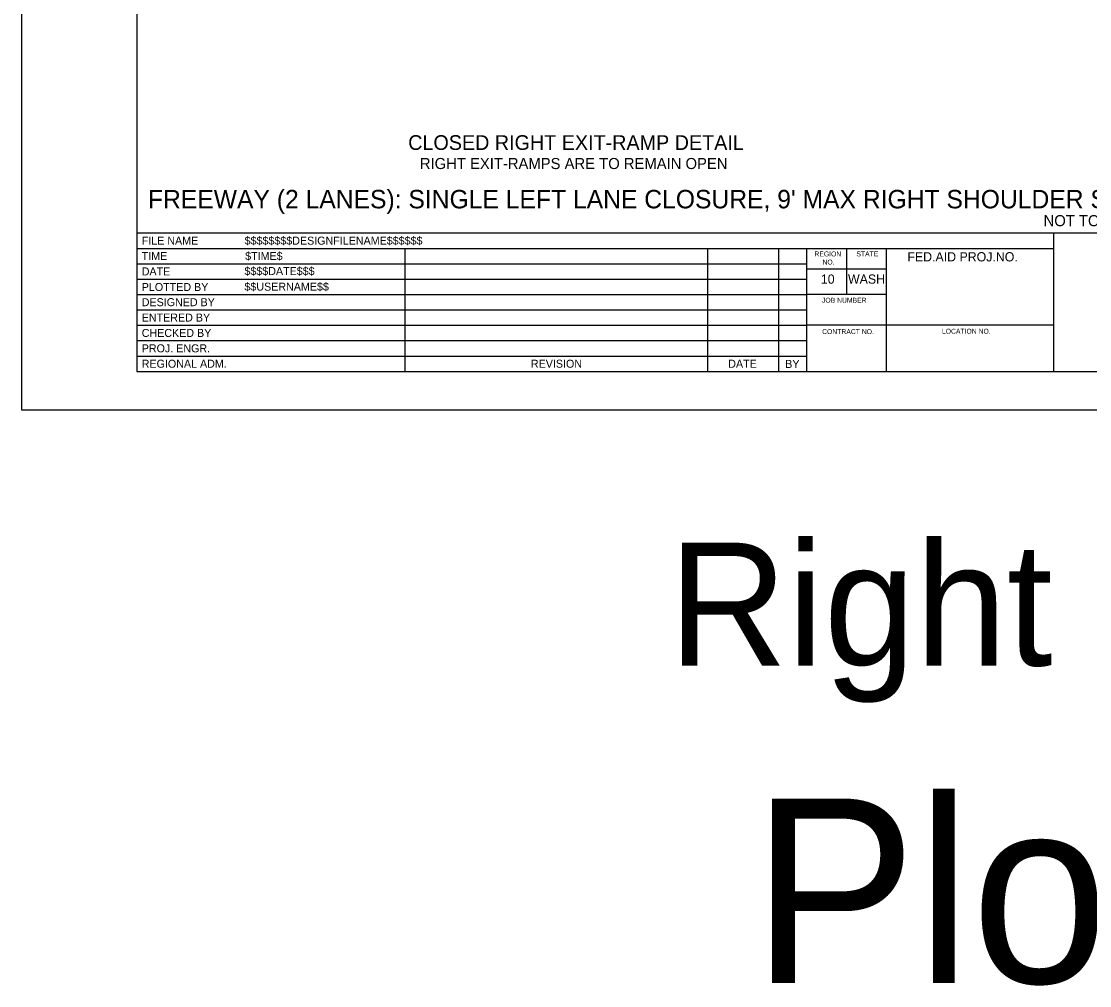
# Model space of a CAD drawing. Extents: x 99999 to 100116, y 99995 to 100013.
# Drawn here: x 100039.06 to 100047.75, y 99995.01 to 100002.85 of the extents above; entities that cross this region are included whole.
import ezdxf

# ---------------------------------------------------------------- set-up
doc = ezdxf.new("R2010")
doc.units = 0
for name, color, linetype in [('SH_DE_DetailHeading1Text', 7, 'Continuous'), ('SH_DE_DetailHeading2Text', 7, 'Continuous'), ('SH_GI_PlotLimits', 7, 'Continuous'), ('SH_GI_SheetBorder', 7, 'Continuous'), ('SH_GI_SheetLocationText', 7, 'Continuous'), ('SH_GI_SheetTextInCells', 7, 'Continuous'), ('SH_GI_TitleBlockText', 7, 'Continuous')]:
    doc.layers.add(name, color=color, linetype=linetype)

msp = doc.modelspace()

# ---------------------------------------------------------------- linework, layer by layer
at = {"layer": 'SH_GI_PlotLimits'}
msp.add_lwpolyline([(100039.0625, 99999.6875), (100056.0625, 99999.6875), (100056.0625, 100010.6875), (100039.0625, 100010.6875)], close=True, dxfattribs=at)
at = {"layer": 'SH_GI_SheetBorder'}
for p, q in [((100040, 100010.375), (100040, 100000)), ((100040, 100001.1259), (100055.75, 100001.1259)), ((100047.4566, 100000), (100047.4566, 100001.1259)), ((100040, 100001.0008), (100047.4566, 100001.0008)), ((100042.179, 100001.0008), (100042.179, 100000)), ((100044.641, 100001.0008), (100044.641, 100000)), ((100045.2164, 100001.0008), (100045.2164, 100000)), ((100045.4451, 100001.0008), (100045.4451, 100000)), ((100045.7719, 100000.6255), (100045.7719, 100001.0008)), ((100046.0956, 100000), (100046.0956, 100001.0008)), ((100040, 100000.8757), (100042.1821, 100000.8757)), ((100042.1821, 100000.8757), (100045.4466, 100000.8757)), ((100046.0958, 100000.831), (100045.4466, 100000.831)), ((100040, 100000.7506), (100042.1821, 100000.7506)), ((100042.1821, 100000.7506), (100045.4466, 100000.7506)), ((100040, 100000.6255), (100045.4466, 100000.6255)), ((100046.0958, 100000.6255), (100045.4466, 100000.6255)), ((100040, 100000.5004), (100045.4466, 100000.5004)), ((100040, 100000.3753), (100045.4466, 100000.3753)), ((100047.4566, 100000.3753), (100045.4466, 100000.3753)), ((100040, 100000.2502), (100045.4466, 100000.2502)), ((100040, 100000.1251), (100045.4466, 100000.1251)), ((100040, 100000), (100055.75, 100000))]:
    msp.add_line(p, q, dxfattribs=at)

# ---------------------------------------------------------------- texts
at = {"layer": 'SH_DE_DetailHeading1Text'}
for s, height, p in [("FREEWAY (2 LANES): SINGLE LEFT LANE CLOSURE, 9' MAX RIGHT SHOULDER SHIFT (45 MPH WORK ZONE SPEED LIMIT, 40 MPH ADVISORY SPEED)", 0.15, (100040.0913, 100001.3259)), ('NOT TO SCALE', 0.09, (100047.3727, 100001.1809))]:
    msp.add_text(s, height=height, rotation=360, dxfattribs=at).set_placement(p)
at = {"layer": 'SH_DE_DetailHeading2Text'}
for s, height, p in [('CLOSED RIGHT EXIT-RAMP DETAIL', 0.12, (100042.2073, 100001.8009)), ('RIGHT EXIT-RAMPS ARE TO REMAIN OPEN', 0.09, (100042.302, 100001.6455))]:
    msp.add_text(s, height=height, rotation=360, dxfattribs=at).set_placement(p)
at = {"layer": 'SH_GI_SheetLocationText'}
for s, height, p in [('Right Ramps', 1, (100044.324, 99997.6071)), ('Plot 3', 1.5, (100045.0008, 99995.0267))]:
    msp.add_text(s, height=height, dxfattribs=at).set_placement(p)
at = {"layer": 'SH_GI_SheetTextInCells'}
for s, height, p in [('FILE NAME', 0.06505, (100040.041, 100001.0308)), ('TIME', 0.06505, (100040.041, 100000.9057)), ('REGION', 0.04003, (100045.5099, 100000.9352)), ('STATE', 0.04003, (100045.8511, 100000.9357)), ('FED.AID PROJ.NO.', 0.07506, (100046.2652, 100000.8945)), ('NO.', 0.04003, (100045.5752, 100000.869)), ('DATE', 0.06505, (100040.041, 100000.7806)), ('10', 0.07506, (100045.5621, 100000.7131)), ('WASH', 0.07506, (100045.7826, 100000.7131)), ('PLOTTED BY', 0.06505, (100040.041, 100000.6538)), ('DESIGNED BY', 0.065052, (100040.041, 100000.5304)), ('JOB NUMBER', 0.04003, (100045.5712, 100000.5587)), ('ENTERED BY', 0.06505, (100040.041, 100000.4053)), ('CHECKED BY', 0.06505, (100040.041, 100000.2802)), ('CONTRACT NO.', 0.040032, (100045.5725, 100000.3037)), ('LOCATION NO.', 0.040032, (100046.5465, 100000.3067)), ('PROJ. ENGR.', 0.065052, (100040.041, 100000.1551)), ('REGIONAL ADM.', 0.065052, (100040.041, 100000.03)), ('REVISION', 0.06505, (100043.2048, 100000.03)), ('DATE', 0.06505, (100044.8091, 100000.03)), ('BY', 0.06505, (100045.2725, 100000.0285))]:
    msp.add_text(s, height=height, dxfattribs=at).set_placement(p)
at = {"layer": 'SH_GI_TitleBlockText'}
for s, height, p in [('$$$$$$$$DESIGNFILENAME$$$$$$', 0.065052, (100040.8775, 100001.0308)), ('$TIME$', 0.06505, (100040.882, 100000.9059)), ('$$$$DATE$$$', 0.065052, (100040.8759, 100000.7835)), ('$$USERNAME$$', 0.065052, (100040.8759, 100000.6567))]:
    msp.add_text(s, height=height, dxfattribs=at).set_placement(p)

doc.saveas('drawing.dxf')
